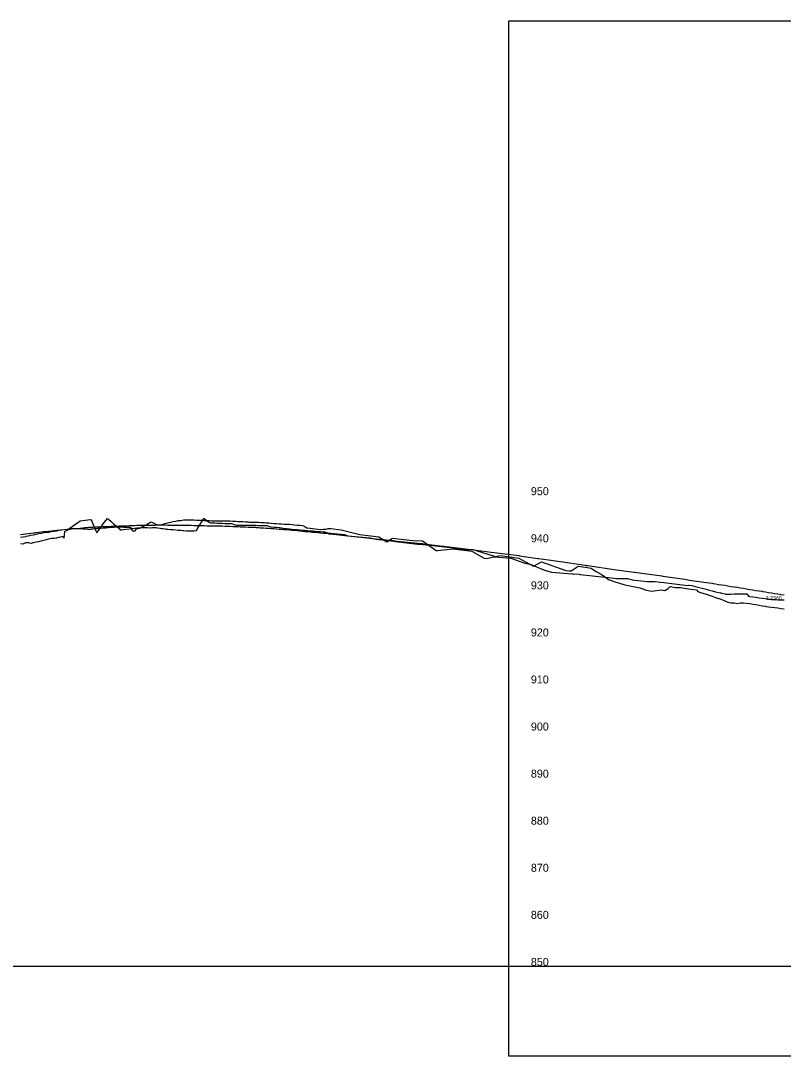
# Model space of a CAD drawing. Extents: x 1558113 to 1562835, y 1129435 to 1135883.
# Drawn here: x 1559007 to 1559817, y 1133348 to 1134448 of the extents above; entities that cross this region are included whole.
import ezdxf

# ---------------------------------------------------------------- set-up
doc = ezdxf.new("R2010")
doc.units = 0
for name, color, linetype in [('BR_EXIST_GROUND_LT', 7, 'Continuous'), ('BR_EXIST_GROUND_RT', 7, 'Continuous'), ('BR_USER NOTES', 7, 'Continuous'), ('RD_DDB_ElevTX', 7, 'Continuous'), ('RD_DDB_Profile_EX', 7, 'Continuous'), ('RD_GPK_Profile_Cell', 7, 'Continuous'), ('RD_SHT_ShtClip', 7, 'Continuous')]:
    doc.layers.add(name, color=color, linetype=linetype)

msp = doc.modelspace()

# ---------------------------------------------------------------- linework, layer by layer
at = {"layer": 'BR_EXIST_GROUND_LT'}
msp.add_lwpolyline([(1559006.4, 1133899.7), (1559009.2, 1133900), (1559011.9, 1133900.4), (1559012.4, 1133900.5), (1559014.7, 1133901), (1559017.4, 1133901.5), (1559020.2, 1133902.1), (1559022.9, 1133902.7), (1559025.7, 1133903.3), (1559028.4, 1133903.8), (1559031.2, 1133904.4), (1559031.8, 1133904.6), (1559033.9, 1133904.8), (1559036.6, 1133905), (1559037.8, 1133905.1), (1559039.4, 1133905.4), (1559042.1, 1133905.9), (1559044.9, 1133906.3), (1559047.6, 1133906.8), (1559050.4, 1133907.3), (1559053.1, 1133907.8), (1559055.9, 1133908.2), (1559058.8, 1133908.8), (1559060.6, 1133909), (1559061.4, 1133908.9), (1559064.1, 1133908.9), (1559066.5, 1133908.8), (1559066.9, 1133908.8), (1559069.6, 1133908.6), (1559072.4, 1133908.4), (1559075.1, 1133908.3), (1559077.8, 1133908.1), (1559080.7, 1133908), (1559081.6, 1133908.4), (1559083.3, 1133908.5), (1559086.1, 1133908.8), (1559087.1, 1133908.9), (1559088.8, 1133909), (1559091.6, 1133909.2), (1559094.3, 1133909.4), (1559097.1, 1133909.6), (1559099.8, 1133909.8), (1559102.6, 1133910), (1559105.3, 1133910.2), (1559108.1, 1133910.4), (1559109.8, 1133910.6), (1559110.8, 1133910.5), (1559113.5, 1133910.4), (1559116.3, 1133910.3), (1559119, 1133910.1), (1559121.8, 1133910), (1559122.8, 1133910), (1559124.5, 1133907.3), (1559125.2, 1133906.2), (1559127.3, 1133906.1), (1559128, 1133906.1), (1559129.2, 1133908.2), (1559130, 1133908.4), (1559132.8, 1133909.1), (1559133.3, 1133909.2), (1559135.5, 1133910.4), (1559138.3, 1133911.9), (1559141, 1133913.4), (1559143.8, 1133915), (1559145.3, 1133915.8), (1559146.5, 1133915.1), (1559148.6, 1133913.9), (1559149.3, 1133913.6), (1559152, 1133912.6), (1559152.9, 1133912.2), (1559154.7, 1133912.7), (1559157.5, 1133913.3), (1559160.2, 1133914), (1559163, 1133914.7), (1559165.7, 1133915.3), (1559168.5, 1133916), (1559171.2, 1133916.6), (1559172.8, 1133917), (1559174, 1133917.1), (1559176.7, 1133917.4), (1559179.5, 1133917.8), (1559181.7, 1133918), (1559182.2, 1133918), (1559185, 1133917.9), (1559187.7, 1133917.8), (1559190.4, 1133917.8), (1559193.2, 1133917.7), (1559195.9, 1133917.6), (1559197.7, 1133917.5), (1559198.7, 1133917.5), (1559201.4, 1133917.4), (1559204.2, 1133917.2), (1559206.9, 1133917.1), (1559209.7, 1133917), (1559212.4, 1133916.8), (1559213.8, 1133916.8), (1559215.2, 1133916.8), (1559217.9, 1133916.8), (1559220.7, 1133916.8), (1559223.4, 1133916.9), (1559226.1, 1133916.9), (1559227.8, 1133916.9), (1559228.9, 1133916.8), (1559231.6, 1133916.7), (1559234.4, 1133916.5), (1559235.1, 1133916.5), (1559237.1, 1133916.3), (1559239.9, 1133916.2), (1559242.6, 1133916), (1559245.4, 1133915.9), (1559248.1, 1133915.7), (1559249.2, 1133915.6), (1559250.9, 1133915.6), (1559253.6, 1133915.5), (1559256.4, 1133915.4), (1559259.1, 1133915.3), (1559261.9, 1133915.2), (1559264.6, 1133915), (1559265.6, 1133915), (1559267.3, 1133914.9), (1559270.1, 1133914.6), (1559272.8, 1133914.4), (1559275.6, 1133914.2), (1559278.3, 1133914), (1559281.1, 1133913.7), (1559282.5, 1133913.6), (1559283.8, 1133913.6), (1559286.6, 1133913.5), (1559289.3, 1133913.4), (1559291.4, 1133913.4), (1559292.1, 1133913.3), (1559294.8, 1133913), (1559297.6, 1133912.7), (1559300.3, 1133912.4), (1559303, 1133912.1), (1559305.8, 1133911.8), (1559307.1, 1133911.7), (1559308.5, 1133910.7), (1559310.3, 1133909.4), (1559311.3, 1133909.3), (1559314, 1133909), (1559316.8, 1133908.7), (1559319.5, 1133908.4), (1559322.3, 1133908.1), (1559325, 1133907.8), (1559327.8, 1133907.9), (1559330.5, 1133908), (1559331, 1133908), (1559333.3, 1133908.6), (1559334.1, 1133908.9), (1559336, 1133908.7), (1559347.2, 1133907.4), (1559366.7, 1133902.3), (1559387.2, 1133900), (1559395.7, 1133894.4), (1559401.6, 1133898.4), (1559423.1, 1133895.9), (1559433.4, 1133895.6), (1559448, 1133885.4), (1559449.3, 1133885.2), (1559465.8, 1133887.3), (1559485.9, 1133884.5), (1559499, 1133877.3), (1559501.5, 1133877), (1559516, 1133880.2), (1559535.8, 1133877.3), (1559551.4, 1133868.9), (1559560, 1133873.5), (1559585.8, 1133864.1), (1559589.4, 1133863.6), (1559591.4, 1133863.7), (1559599, 1133868.6), (1559606.4, 1133867.6), (1559612.7, 1133866.7), (1559617.3, 1133863.5), (1559623.1, 1133860.4), (1559626.7, 1133857.8), (1559631, 1133854.5), (1559638.3, 1133852), (1559648.3, 1133849), (1559664.5, 1133845.7), (1559671.4, 1133843.2), (1559673.1, 1133842.8), (1559677, 1133842), (1559687.4, 1133843.5), (1559691, 1133842.7), (1559694.5, 1133845), (1559696.4, 1133847.2), (1559702.3, 1133845.9), (1559707.5, 1133845.9), (1559716.2, 1133844.5), (1559724.4, 1133843.7), (1559725.9, 1133841.7), (1559727.6, 1133841.2), (1559734.7, 1133838.9), (1559738, 1133837.8), (1559741.3, 1133836.7), (1559744.6, 1133835.6), (1559748, 1133834.5), (1559748.5, 1133834.3), (1559751.3, 1133833.2), (1559754.6, 1133831.9), (1559757.9, 1133830.6), (1559759.1, 1133830.2), (1559761.2, 1133829.9), (1559764.5, 1133829.6), (1559767.9, 1133829.2), (1559771.2, 1133829.6), (1559774.6, 1133829.9), (1559777.8, 1133829.5), (1559781.1, 1133828.9), (1559784.4, 1133828.4), (1559787.7, 1133827.9), (1559791, 1133827.3), (1559794.4, 1133826.7), (1559797.7, 1133826.1), (1559798.7, 1133825.9), (1559801, 1133825.4), (1559804.3, 1133825), (1559807.6, 1133824.7), (1559810.9, 1133824.3), (1559814.2, 1133823.9), (1559817.6, 1133823.5)], dxfattribs=at)
at = {"layer": 'BR_EXIST_GROUND_RT'}
msp.add_lwpolyline([(1559006.4, 1133892.7), (1559008.7, 1133892.4), (1559009.2, 1133892.6), (1559012, 1133893.7), (1559013.7, 1133893.9), (1559014.7, 1133893.8), (1559017.4, 1133893.3), (1559018.1, 1133893.2), (1559020.2, 1133893.7), (1559022.9, 1133894.4), (1559025.7, 1133895), (1559028.4, 1133895.7), (1559031.2, 1133896.3), (1559033.9, 1133897), (1559036.6, 1133897.6), (1559039.4, 1133898.3), (1559042.1, 1133898.6), (1559044.1, 1133898.8), (1559044.9, 1133898.9), (1559047.6, 1133899.5), (1559050.4, 1133900.1), (1559051.4, 1133900.3), (1559052.6, 1133898.4), (1559053.4, 1133905.4), (1559055.9, 1133907.1), (1559058.6, 1133909), (1559061.4, 1133911), (1559064.1, 1133912.9), (1559066.9, 1133914.9), (1559069.6, 1133916.9), (1559072.4, 1133917.2), (1559075.1, 1133917.5), (1559077.8, 1133917.8), (1559080.6, 1133918.2), (1559081.5, 1133918.3), (1559083.3, 1133913.8), (1559086.1, 1133907.1), (1559087.3, 1133904.3), (1559088.8, 1133906.3), (1559091.6, 1133909.9), (1559094.3, 1133913.6), (1559097.1, 1133917.3), (1559098.7, 1133919.5), (1559099.8, 1133918.5), (1559102.6, 1133916.1), (1559105.3, 1133913.8), (1559108.1, 1133911.5), (1559110.8, 1133909.1), (1559112.4, 1133907.3), (1559113.5, 1133907.4), (1559116.3, 1133907.7), (1559119, 1133908), (1559121.8, 1133908.3), (1559124.5, 1133908.6), (1559127.3, 1133909), (1559130, 1133909.3), (1559132.8, 1133909.6), (1559134.7, 1133909.8), (1559135, 1133909.8), (1559135.5, 1133909.8), (1559138.3, 1133909.7), (1559141, 1133909.7), (1559143.8, 1133909.6), (1559144.3, 1133909.6), (1559146.5, 1133909.7), (1559149.3, 1133909.7), (1559150.6, 1133909.7), (1559152, 1133909.5), (1559154.7, 1133909.1), (1559156.2, 1133908.9), (1559157.5, 1133908.7), (1559160.2, 1133908.3), (1559161, 1133908.1), (1559163, 1133908), (1559165.7, 1133907.7), (1559168.5, 1133907.5), (1559171.2, 1133907.3), (1559174, 1133907.1), (1559176.7, 1133906.8), (1559178.4, 1133906.7), (1559179.5, 1133906.6), (1559182.2, 1133906.4), (1559184.6, 1133906.2), (1559185, 1133906.2), (1559187.7, 1133906.3), (1559190.4, 1133906.4), (1559193.2, 1133906.5), (1559195.9, 1133911), (1559198.7, 1133915.5), (1559201.1, 1133919.5), (1559201.4, 1133919.2), (1559204.2, 1133917.4), (1559206.9, 1133915.6), (1559208.2, 1133914.8), (1559209.7, 1133914.8), (1559212.4, 1133914.6), (1559215.2, 1133914.5), (1559217.9, 1133914.4), (1559220.7, 1133914.3), (1559223.4, 1133914.2), (1559226.1, 1133914.1), (1559228.9, 1133914.1), (1559230.6, 1133914), (1559231.6, 1133913.6), (1559233.3, 1133913), (1559234.4, 1133912.7), (1559236.2, 1133912.3), (1559237.1, 1133912.3), (1559239.9, 1133912.3), (1559242.6, 1133912.2), (1559245.4, 1133912.2), (1559248.1, 1133912.2), (1559250.9, 1133912.2), (1559252.3, 1133912.2), (1559253.6, 1133912.1), (1559256.4, 1133912.1), (1559259.1, 1133912), (1559261.9, 1133912), (1559264.6, 1133911.9), (1559267.3, 1133911.9), (1559268.2, 1133911.9), (1559270.1, 1133911.2), (1559271.5, 1133910.6), (1559272.8, 1133910.5), (1559275.6, 1133910.3), (1559278.3, 1133910.1), (1559281.1, 1133909.9), (1559282, 1133909.9), (1559283.8, 1133909.3), (1559284.8, 1133909), (1559286.6, 1133908.8), (1559289.3, 1133908.6), (1559292.1, 1133908.3), (1559294.8, 1133908.1), (1559297.6, 1133907.8), (1559300.3, 1133907.6), (1559303, 1133907.3), (1559305.3, 1133907.1), (1559305.8, 1133907.1), (1559308.5, 1133906.8), (1559309.7, 1133906.6), (1559311.3, 1133906.5), (1559314, 1133906.3), (1559316.8, 1133906.1), (1559319.5, 1133905.8), (1559322.3, 1133905.6), (1559325, 1133905.4), (1559327.8, 1133905.2), (1559329.8, 1133905.1), (1559330.5, 1133904.9), (1559333.3, 1133904.1), (1559335, 1133903.6), (1559336, 1133903.6), (1559350.5, 1133902.4), (1559354, 1133901), (1559377.9, 1133898.9), (1559383.8, 1133897.5), (1559400.1, 1133895.8), (1559404.8, 1133894.8), (1559428.3, 1133892.2), (1559434, 1133891.6), (1559450.5, 1133889.8), (1559456.8, 1133889.2), (1559480.6, 1133886.6), (1559487, 1133886.4), (1559507.6, 1133879.9), (1559509.1, 1133879.8), (1559509.6, 1133879.6), (1559510, 1133878.8), (1559527.2, 1133877.2), (1559542.1, 1133871.8), (1559548, 1133870.7), (1559563, 1133864.5), (1559564.3, 1133864.2), (1559570.5, 1133862.5), (1559592.3, 1133860.7), (1559593.9, 1133860.6), (1559599.9, 1133860.1), (1559600.9, 1133859.9), (1559627, 1133857.2), (1559630.9, 1133856.7), (1559639.6, 1133855.8), (1559640.1, 1133855.8), (1559651.4, 1133855.8), (1559656.1, 1133854.1), (1559672, 1133852.3), (1559680.8, 1133852.4), (1559686, 1133851.8), (1559690, 1133851.2), (1559715.2, 1133848.2), (1559716.1, 1133848.6), (1559719.6, 1133848.1), (1559723.2, 1133847.2), (1559734.7, 1133844.2), (1559738, 1133843.3), (1559741.3, 1133842.5), (1559744.6, 1133841.6), (1559748, 1133840.8), (1559749.8, 1133840.3), (1559750.3, 1133840.4), (1559751.3, 1133840.1), (1559754.6, 1133839.2), (1559755.3, 1133839), (1559757.9, 1133839.1), (1559761.2, 1133839.1), (1559764.5, 1133839.2), (1559767.8, 1133839.2), (1559771.2, 1133839.3), (1559774.5, 1133839.4), (1559778, 1133839.5), (1559779.8, 1133836.8), (1559781.1, 1133836.6), (1559784.4, 1133836.2), (1559787.7, 1133835.7), (1559791, 1133835.2), (1559794.4, 1133834.8), (1559797.7, 1133834.3), (1559801, 1133833.8), (1559803.2, 1133833.5), (1559804.3, 1133833.4), (1559807.6, 1133833.3), (1559808.1, 1133833.3), (1559809.4, 1133833.2), (1559810.9, 1133833.1), (1559814.2, 1133833), (1559817.6, 1133832.9)], dxfattribs=at)
at = {"layer": 'RD_DDB_Profile_EX'}
msp.add_lwpolyline([(1559006.4, 1133902.3), (1559009.2, 1133902.6), (1559011.9, 1133903), (1559014.7, 1133903.3), (1559017.4, 1133903.7), (1559020.2, 1133904), (1559022, 1133904.3), (1559022.9, 1133904.4), (1559025.9, 1133904.9), (1559028.4, 1133905.1), (1559031.2, 1133905.4), (1559033.9, 1133905.7), (1559036.6, 1133905.9), (1559039.4, 1133906.2), (1559042.1, 1133906.5), (1559044.9, 1133906.8), (1559047.6, 1133907.1), (1559048.8, 1133907.2), (1559050.4, 1133907.3), (1559053.1, 1133907.6), (1559055.9, 1133907.9), (1559058.6, 1133908.1), (1559061.4, 1133908.4), (1559064.1, 1133908.6), (1559066.9, 1133908.9), (1559069.6, 1133909.1), (1559072.4, 1133909.4), (1559074.4, 1133909.6), (1559075.1, 1133909.7), (1559077.8, 1133909.9), (1559078.8, 1133910), (1559080.6, 1133910.1), (1559083.3, 1133910.2), (1559086.1, 1133910.4), (1559088.8, 1133910.5), (1559091.6, 1133910.6), (1559094.3, 1133910.7), (1559097.1, 1133910.8), (1559099.8, 1133911), (1559102.6, 1133911.1), (1559104.9, 1133911.2), (1559105.3, 1133911.2), (1559108.1, 1133911.3), (1559110.8, 1133911.4), (1559113.5, 1133911.5), (1559116.3, 1133911.6), (1559119, 1133911.7), (1559121.8, 1133911.8), (1559124.5, 1133911.9), (1559125.2, 1133911.9), (1559127.3, 1133912), (1559130, 1133912.1), (1559130.9, 1133912.2), (1559132.8, 1133912.2), (1559134.8, 1133912.3), (1559135.5, 1133912.3), (1559138.3, 1133912.3), (1559141, 1133912.4), (1559143.8, 1133912.4), (1559146.5, 1133912.4), (1559149.3, 1133912.4), (1559152, 1133912.5), (1559154.1, 1133912.5), (1559154.7, 1133912.5), (1559157.5, 1133912.5), (1559160.2, 1133912.5), (1559163, 1133912.4), (1559165.7, 1133912.4), (1559168.5, 1133912.4), (1559171.2, 1133912.3), (1559174, 1133912.3), (1559176.7, 1133912.2), (1559177.6, 1133912.2), (1559179.5, 1133912.2), (1559182.2, 1133912.2), (1559185, 1133912.1), (1559187.7, 1133912.1), (1559190.4, 1133912), (1559190.8, 1133912), (1559193.2, 1133911.9), (1559194.5, 1133911.9), (1559195.9, 1133911.9), (1559198.7, 1133911.8), (1559201.4, 1133911.8), (1559204.2, 1133911.7), (1559205.7, 1133911.7), (1559206.9, 1133911.7), (1559209.7, 1133911.6), (1559212.4, 1133911.6), (1559215.2, 1133911.5), (1559217.9, 1133911.5), (1559220.7, 1133911.4), (1559223.4, 1133911.3), (1559226.1, 1133911.3), (1559228, 1133911.2), (1559228.9, 1133911.2), (1559231.9, 1133911), (1559234.4, 1133910.9), (1559235.1, 1133910.8), (1559237.1, 1133910.7), (1559239.9, 1133910.6), (1559242.6, 1133910.5), (1559245.4, 1133910.4), (1559248.1, 1133910.3), (1559250.9, 1133910.2), (1559253.6, 1133910.1), (1559256.4, 1133910), (1559256.9, 1133909.9), (1559259.1, 1133909.8), (1559261.1, 1133909.6), (1559261.9, 1133909.6), (1559264.6, 1133909.4), (1559267.3, 1133909.2), (1559270.1, 1133909), (1559272.8, 1133908.8), (1559275.6, 1133908.6), (1559278.3, 1133908.4), (1559281.1, 1133908.2), (1559283, 1133908.1), (1559283.8, 1133908), (1559285.8, 1133907.8), (1559286.6, 1133907.8), (1559289.3, 1133907.5), (1559292.1, 1133907.3), (1559294.8, 1133907), (1559297.6, 1133906.8), (1559300.3, 1133906.5), (1559303, 1133906.3), (1559305.8, 1133906), (1559307.5, 1133905.9), (1559308.5, 1133905.7), (1559311.3, 1133905.5), (1559314, 1133905.2), (1559316.8, 1133905), (1559319.5, 1133904.7), (1559322.3, 1133904.4), (1559325, 1133904.2), (1559327.8, 1133903.9), (1559330.5, 1133903.6), (1559333.3, 1133903.3), (1559334.1, 1133903.2), (1559336, 1133903), (1559353.6, 1133901.1), (1559354.1, 1133901), (1559367.8, 1133899.5), (1559383.6, 1133897.8), (1559402.6, 1133895.9), (1559403.2, 1133895.8), (1559431.9, 1133892.9), (1559433.2, 1133892.7), (1559434.2, 1133892.6), (1559455.3, 1133890.1), (1559456, 1133890), (1559478.9, 1133887.3), (1559485.3, 1133886.5), (1559506.5, 1133883.7), (1559535.8, 1133879.9), (1559536.5, 1133879.8), (1559556.1, 1133877), (1559557, 1133876.8), (1559584.9, 1133872.8), (1559587, 1133872.5), (1559606.1, 1133869.7), (1559607.2, 1133869.6), (1559609, 1133869.3), (1559637.2, 1133865.3), (1559657.8, 1133862.4), (1559658.7, 1133862.3), (1559687.8, 1133858.3), (1559688.7, 1133858.2), (1559712.1, 1133854.8), (1559717.1, 1133854), (1559734.7, 1133851.4), (1559738, 1133851), (1559741.3, 1133850.5), (1559742.1, 1133850.4), (1559742.7, 1133850.3), (1559744.6, 1133850), (1559748, 1133849.4), (1559751.3, 1133848.9), (1559754.6, 1133848.4), (1559757.9, 1133847.9), (1559761.2, 1133847.3), (1559764.5, 1133846.8), (1559765, 1133846.7), (1559767.8, 1133846.3), (1559771.2, 1133845.7), (1559774.5, 1133845.2), (1559777.8, 1133844.7), (1559781.1, 1133844.1), (1559784.4, 1133843.6), (1559787.7, 1133843), (1559791, 1133842.5), (1559794, 1133842), (1559794.4, 1133842), (1559795, 1133841.9), (1559797.7, 1133841.4), (1559801, 1133840.9), (1559804.3, 1133840.4), (1559807.6, 1133839.8), (1559810.9, 1133839.3), (1559814.2, 1133838.7), (1559817.6, 1133838.2)], dxfattribs=at)
at = {"layer": 'RD_GPK_Profile_Cell'}
msp.add_line((1558196.4, 1133443.8), (1562834.7, 1133443.8), dxfattribs=at)
at = {"layer": 'RD_SHT_ShtClip'}
msp.add_lwpolyline([(1559525.2, 1134448.1), (1561325.2, 1134448.1), (1561325.2, 1133348.1), (1559525.2, 1133348.1)], close=True, dxfattribs=at)

# ---------------------------------------------------------------- texts
at = {"layer": 'BR_USER NOTES'}
msp.add_text('-3.3360', height=4, dxfattribs=at).set_placement((1559796.3, 1133832.9))
at = {"layer": 'RD_DDB_ElevTX'}
for s, p in [('950', (1559548.6, 1133944.1)), ('940', (1559548.6, 1133894.1)), ('930', (1559548.6, 1133844.1)), ('920', (1559548.6, 1133794.1)), ('910', (1559548.6, 1133744.1)), ('900', (1559548.6, 1133694.1)), ('890', (1559548.6, 1133644.1)), ('880', (1559548.6, 1133594.1)), ('870', (1559548.6, 1133544.1)), ('860', (1559548.6, 1133494.1)), ('850', (1559548.6, 1133444.1))]:
    msp.add_text(s, height=8.5, dxfattribs=at).set_placement(p)

doc.saveas('drawing.dxf')
